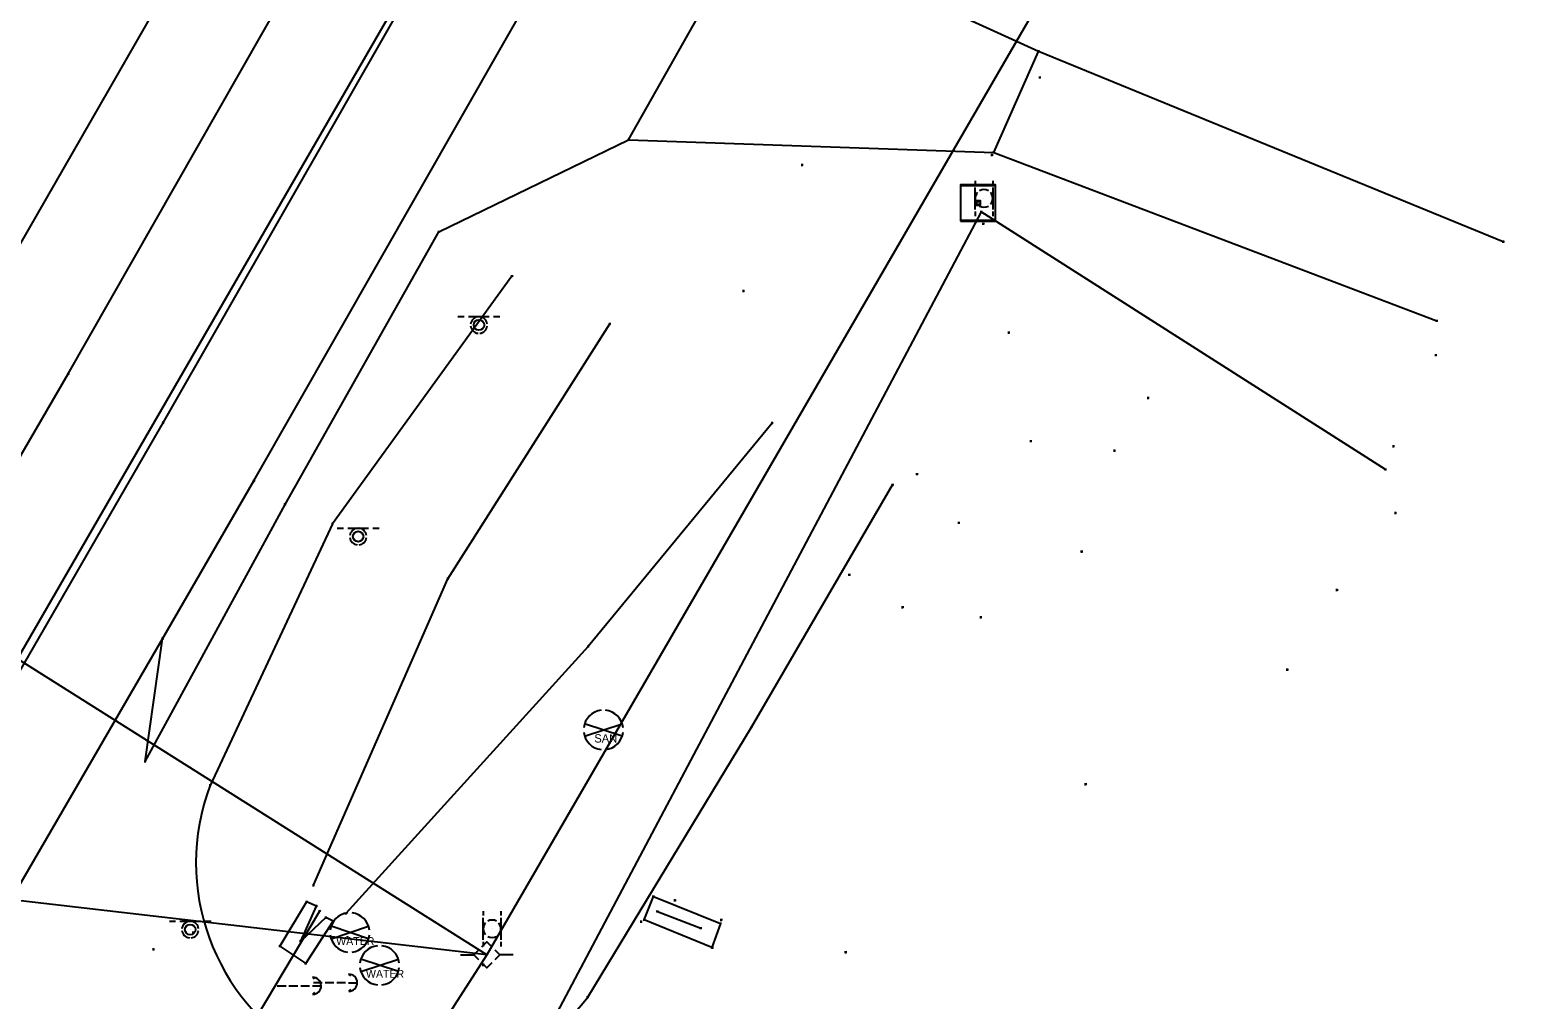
# Model space of a CAD drawing. Extents: x 1954856 to 2011933, y 399149 to 426294.
# Drawn here: x 2007162.2 to 2007333.7, y 403170.4 to 403280.8 of the extents above; entities that cross this region are included whole.
import ezdxf

# ---------------------------------------------------------------- set-up
doc = ezdxf.new("R2010")
doc.units = 0
for name, color, linetype in [('BankMent_ep', 7, 'Continuous'), ('BaselineSurvey', 7, 'Continuous'), ('ConcSlabs_ep', 7, 'Continuous'), ('DelineatorPost_ep', 7, 'Continuous'), ('Driveway_ep', 7, 'Continuous'), ('ElecAer_ep', 7, 'Continuous'), ('EndTreatMES_ep', 7, 'Continuous'), ('Fence_ep', 7, 'Continuous'), ('FlowLineInvert_ep', 7, 'Continuous'), ('GuyWireAnchor_ep', 7, 'Continuous'), ('MonumentCC_ep', 7, 'Continuous'), ('PavtAsphalt_ep', 7, 'Continuous'), ('PavtAsphaltCrown_ep', 7, 'Continuous'), ('PipeCulvert_ep', 7, 'Continuous'), ('PMRK_ep', 7, 'Continuous'), ('PointLocator_ep', 7, 'Continuous'), ('PoleElec_ep', 7, 'Continuous'), ('ShldrPaved_ep', 7, 'Continuous'), ('SignSingle_ep', 7, 'Continuous'), ('Trail_ep', 7, 'Continuous'), ('ValveCvrSewer_ep', 7, 'Continuous'), ('ValveCvrWater_ep', 7, 'Continuous'), ('WaterB_ep', 7, 'Continuous')]:
    doc.layers.add(name, color=color, linetype=linetype)

msp = doc.modelspace()

# ---------------------------------------------------------------- linework, layer by layer
at = {"layer": 'BankMent_ep'}
for p, q in [((2007216.98, 403252.81), (2007196.55, 403224.61)), ((2007244.24, 403201.46), (2007260.29, 403229.04)), ((2007196.55, 403224.61), (2007182.65, 403194.84)), ((2007225.6, 403170.73), (2007244.24, 403201.46))]:
    msp.add_line(p, q, dxfattribs=at)
for points in [[(2007194.39, 403183.47), (2007209.69, 403218.36), (2007228.12, 403247.37)], [(2007246.58, 403236.08), (2007225.66, 403210.64), (2007198.08, 403180.25)]]:
    msp.add_lwpolyline(points, dxfattribs=at)
msp.add_arc((2007205.94, 403186.01), 24.91, 159.2289, 322.1605, dxfattribs=at)
at = {"layer": 'BaselineSurvey'}
msp.add_lwpolyline([(2006095.1, 401364.22), (2006751.44, 402500.64), (2007687.69, 404121.69)], dxfattribs=at)
at = {"layer": 'ConcSlabs_ep'}
msp.add_lwpolyline([(2007240.7, 403179.12), (2007239.72, 403176.38), (2007232.04, 403179.54), (2007233.08, 403182.17)], close=True, dxfattribs=at)
at = {"layer": 'DelineatorPost_ep'}
for p, q in [((2007269.69, 403263.66), (2007269.69, 403263.16)), ((2007271.69, 403263.66), (2007271.69, 403263.16)), ((2007269.69, 403260.41), (2007269.69, 403262.91)), ((2007271.69, 403262.91), (2007271.69, 403260.41)), ((2007270.69, 403261.66), (2007270.69, 403261.66)), ((2007269.69, 403260.16), (2007269.69, 403259.66)), ((2007271.69, 403260.16), (2007271.69, 403259.66)), ((2007213.72, 403180.51), (2007213.72, 403180.01)), ((2007213.72, 403177.26), (2007213.72, 403179.76)), ((2007215.72, 403180.51), (2007215.72, 403180.01)), ((2007215.72, 403179.76), (2007215.72, 403177.26)), ((2007214.72, 403178.51), (2007214.72, 403178.51)), ((2007213.72, 403177.01), (2007213.72, 403176.51)), ((2007215.72, 403177.01), (2007215.72, 403176.51))]:
    msp.add_line(p, q, dxfattribs=at)
for centre, start, end in [((2007270.69, 403261.66), 138.5904, 221.4096), ((2007270.69, 403261.66), 60, 120), ((2007270.69, 403261.66), 318.5904, 41.4096), ((2007270.69, 403261.66), 240, 300), ((2007214.72, 403178.51), 138.5904, 221.4096), ((2007214.72, 403178.51), 60, 120), ((2007214.72, 403178.51), 318.5904, 41.4096), ((2007214.72, 403178.51), 240, 300)]:
    msp.add_arc(centre, 1, start, end, dxfattribs=at)
at = {"layer": 'Driveway_ep'}
msp.add_lwpolyline([(2007230.25, 403268.33), (2007271.8, 403266.88), (2007276.91, 403278.4), (2007244.3, 403293.28)], dxfattribs=at)
at = {"layer": 'ElecAer_ep'}
for points in [[(2007708.74, 404031.96), (2007465.98, 403610.27), (2007214.12, 403175.55), (2007112.5, 403239.66)], [(2007214.12, 403175.55), (2007004.92, 403199.79)], [(2007214.12, 403175.55), (2007202.74, 403157.81)]]:
    msp.add_lwpolyline(points, dxfattribs=at)
at = {"layer": 'EndTreatMES_ep'}
msp.add_lwpolyline([(2007193.61, 403181.59), (2007190.58, 403176.53), (2007193.51, 403174.56), (2007196.65, 403179.36), (2007195.79, 403179.78), (2007192.94, 403177.09), (2007194.74, 403181.1)], close=True, dxfattribs=at)
at = {"layer": 'Fence_ep'}
msp.add_lwpolyline([(2007316.39, 403230.79), (2007270.37, 403260.12), (2007212.64, 403151.1)], dxfattribs=at)
at = {"layer": 'FlowLineInvert_ep'}
for p, q in [((2007195.18, 403180.4), (2007195, 403180.58)), ((2007195.18, 403180.58), (2007195, 403180.4)), ((2007195.09, 403180.49), (2007195.09, 403180.49))]:
    msp.add_line(p, q, dxfattribs=at)
at = {"layer": 'GuyWireAnchor_ep'}
for p, q in [((2007194.3, 403172.99), (2007194.49, 403172.8)), ((2007198.4, 403173.34), (2007198.6, 403173.15)), ((2007190.27, 403172.03), (2007191.27, 403172.03)), ((2007191.6, 403172.03), (2007192.6, 403172.03)), ((2007192.94, 403172.03), (2007193.94, 403172.03)), ((2007194.27, 403172.02), (2007195.27, 403172.02)), ((2007194.31, 403171.05), (2007194.55, 403171.28)), ((2007194.38, 403172.38), (2007195.38, 403172.38)), ((2007195.27, 403172.02), (2007195.27, 403172.02)), ((2007195.71, 403172.38), (2007196.71, 403172.38)), ((2007197.04, 403172.38), (2007198.04, 403172.38)), ((2007198.38, 403172.37), (2007199.38, 403172.37)), ((2007198.42, 403171.4), (2007198.66, 403171.63)), ((2007199.38, 403172.37), (2007199.38, 403172.37))]:
    msp.add_line(p, q, dxfattribs=at)
for centre in [(2007194.3, 403172.02), (2007198.4, 403172.37)]:
    msp.add_arc(centre, 0.973, 271.14, 90.0059, dxfattribs=at)
at = {"layer": 'MonumentCC_ep'}
for p, q in [((2007270.01, 403261.2), (2007270.01, 403261.2)), ((2007270.02, 403261.09), (2007270.02, 403261.09))]:
    msp.add_line(p, q, dxfattribs=at)
for points in [[(2007268.01, 403259.2), (2007272.01, 403259.2), (2007272.01, 403263.2), (2007268.01, 403263.2), (2007268.01, 403259.2)], [(2007268.02, 403259.09), (2007272.02, 403259.09), (2007272.02, 403263.1), (2007268.02, 403263.1), (2007268.02, 403259.09)]]:
    msp.add_lwpolyline(points, dxfattribs=at)
for points in [[(2007269.77, 403260.97), (2007269.77, 403261.44), (2007270.24, 403261.44), (2007270.24, 403260.97)], [(2007269.78, 403260.86), (2007269.78, 403261.33), (2007270.26, 403261.33), (2007270.26, 403260.86)]]:
    msp.add_lwpolyline(points, close=True, dxfattribs=at)
at = {"layer": 'PavtAsphalt_ep'}
msp.add_line((2007175.25, 403197.55), (2007177.23, 403211.53), dxfattribs=at)
for points in [[(2007177.23, 403211.53), (2007187.62, 403229.5), (2007234.7, 403312.11), (2007271.67, 403375.49), (2007306.65, 403435.49), (2007349.66, 403509.58), (2007385.36, 403571.59), (2007428.89, 403647.4), (2007469.25, 403717.9)], [(2006897.05, 402800.14), (2006944.17, 402881.58), (2006996.71, 402973.18), (2007032.59, 403035.44), (2007081.34, 403118.81), (2007155.79, 403247.38), (2007202.92, 403329.48)]]:
    msp.add_lwpolyline(points, dxfattribs=at)
at = {"layer": 'PavtAsphaltCrown_ep'}
msp.add_lwpolyline([(2006917.74, 402787.19), (2006964.28, 402867.82), (2007017.94, 402960.42), (2007054.7, 403023.68), (2007102.51, 403106.5), (2007177.29, 403236.13), (2007223.74, 403317.44)], dxfattribs=at)
at = {"layer": 'PipeCulvert_ep'}
msp.add_lwpolyline([(2007154.82, 403112.92), (2007195.09, 403180.49)], dxfattribs=at)
at = {"layer": 'PMRK_ep'}
for points in [[(2006907.45, 402793.37), (2006954.17, 402875.59), (2007007.43, 402967.36), (2007044.03, 403029.48), (2007091.72, 403112.9), (2007166.49, 403241.69), (2007213.16, 403323.66)], [(2006926.96, 402780.55), (2006975.08, 402862.21), (2007028.52, 402954.63), (2007065.46, 403018.91), (2007177.23, 403211.53)]]:
    msp.add_lwpolyline(points, dxfattribs=at)
at = {"layer": 'PointLocator_ep'}
for p, q in [((2007277.04, 403278.4), (2007276.79, 403278.4)), ((2007276.91, 403278.28), (2007276.91, 403278.53)), ((2007276.91, 403278.4), (2007276.91, 403278.4)), ((2007277.17, 403275.43), (2007276.92, 403275.43)), ((2007277.05, 403275.3), (2007277.05, 403275.55)), ((2007277.05, 403275.43), (2007277.05, 403275.43)), ((2007230.38, 403268.33), (2007230.13, 403268.33)), ((2007230.25, 403268.21), (2007230.25, 403268.46)), ((2007230.25, 403268.33), (2007230.25, 403268.33)), ((2007250.13, 403265.47), (2007249.88, 403265.47)), ((2007250, 403265.34), (2007250, 403265.59)), ((2007250, 403265.47), (2007250, 403265.47)), ((2007271.72, 403266.6), (2007271.47, 403266.6)), ((2007271.59, 403266.48), (2007271.59, 403266.73)), ((2007271.59, 403266.6), (2007271.59, 403266.6)), ((2007271.93, 403266.88), (2007271.68, 403266.88)), ((2007271.8, 403266.76), (2007271.8, 403267.01)), ((2007271.8, 403266.88), (2007271.8, 403266.88)), ((2007270.37, 403260), (2007270.37, 403260.25)), ((2007270.49, 403260.12), (2007270.24, 403260.12)), ((2007270.37, 403260.12), (2007270.37, 403260.12)), ((2007270.74, 403258.77), (2007270.49, 403258.77)), ((2007270.61, 403258.65), (2007270.61, 403258.9)), ((2007270.61, 403258.77), (2007270.61, 403258.77)), ((2007208.8, 403257.87), (2007208.55, 403257.87)), ((2007208.67, 403257.74), (2007208.67, 403257.99)), ((2007208.67, 403257.87), (2007208.67, 403257.87)), ((2007329.79, 403256.61), (2007329.79, 403256.86)), ((2007329.92, 403256.73), (2007329.67, 403256.73)), ((2007329.79, 403256.73), (2007329.79, 403256.73)), ((2007217.11, 403252.81), (2007216.86, 403252.81)), ((2007216.98, 403252.69), (2007216.98, 403252.94)), ((2007216.98, 403252.81), (2007216.98, 403252.81)), ((2007243.45, 403251.12), (2007243.2, 403251.12)), ((2007243.32, 403250.99), (2007243.32, 403251.24)), ((2007243.32, 403251.12), (2007243.32, 403251.12)), ((2007228.24, 403247.37), (2007227.99, 403247.37)), ((2007228.12, 403247.25), (2007228.12, 403247.5)), ((2007228.12, 403247.37), (2007228.12, 403247.37)), ((2007273.53, 403246.25), (2007273.53, 403246.5)), ((2007322.35, 403247.72), (2007322.1, 403247.72)), ((2007322.23, 403247.6), (2007322.23, 403247.85)), ((2007322.23, 403247.72), (2007322.23, 403247.72)), ((2007273.65, 403246.38), (2007273.4, 403246.38)), ((2007273.53, 403246.38), (2007273.53, 403246.38)), ((2007322.24, 403243.81), (2007321.99, 403243.81)), ((2007322.11, 403243.69), (2007322.11, 403243.94)), ((2007322.11, 403243.81), (2007322.11, 403243.81)), ((2007166.62, 403241.69), (2007166.37, 403241.69)), ((2007166.49, 403241.56), (2007166.49, 403241.81)), ((2007166.49, 403241.69), (2007166.49, 403241.69)), ((2007289.5, 403238.95), (2007289.25, 403238.95)), ((2007289.37, 403238.82), (2007289.37, 403239.07)), ((2007289.37, 403238.95), (2007289.37, 403238.95)), ((2007177.29, 403236.01), (2007177.29, 403236.26)), ((2007246.58, 403235.96), (2007246.58, 403236.21)), ((2007177.42, 403236.13), (2007177.17, 403236.13)), ((2007177.29, 403236.13), (2007177.29, 403236.13)), ((2007246.71, 403236.08), (2007246.46, 403236.08)), ((2007246.58, 403236.08), (2007246.58, 403236.08)), ((2007276.15, 403234.03), (2007275.9, 403234.03)), ((2007276.02, 403233.9), (2007276.02, 403234.15)), ((2007276.02, 403234.03), (2007276.02, 403234.03)), ((2007285.67, 403232.94), (2007285.42, 403232.94)), ((2007285.54, 403232.81), (2007285.54, 403233.06)), ((2007285.54, 403232.94), (2007285.54, 403232.94)), ((2007317.41, 403233.44), (2007317.16, 403233.44)), ((2007317.29, 403233.32), (2007317.29, 403233.57)), ((2007317.29, 403233.44), (2007317.29, 403233.44)), ((2007187.75, 403229.5), (2007187.5, 403229.5)), ((2007187.62, 403229.37), (2007187.62, 403229.62)), ((2007187.62, 403229.5), (2007187.62, 403229.5)), ((2007263.2, 403230.28), (2007262.95, 403230.28)), ((2007263.08, 403230.15), (2007263.08, 403230.4)), ((2007263.08, 403230.28), (2007263.08, 403230.28)), ((2007316.51, 403230.79), (2007316.26, 403230.79)), ((2007316.39, 403230.67), (2007316.39, 403230.92)), ((2007316.39, 403230.79), (2007316.39, 403230.79)), ((2007260.42, 403229.04), (2007260.17, 403229.04)), ((2007260.29, 403228.92), (2007260.29, 403229.17)), ((2007260.29, 403229.04), (2007260.29, 403229.04)), ((2007191.29, 403226.83), (2007191.04, 403226.83)), ((2007191.17, 403226.71), (2007191.17, 403226.96)), ((2007191.17, 403226.83), (2007191.17, 403226.83)), ((2007317.52, 403225.72), (2007317.52, 403225.97)), ((2007196.68, 403224.61), (2007196.43, 403224.61)), ((2007196.55, 403224.49), (2007196.55, 403224.74)), ((2007196.55, 403224.61), (2007196.55, 403224.61)), ((2007267.96, 403224.73), (2007267.71, 403224.73)), ((2007267.84, 403224.61), (2007267.84, 403224.86)), ((2007267.84, 403224.73), (2007267.84, 403224.73)), ((2007317.64, 403225.84), (2007317.39, 403225.84)), ((2007317.52, 403225.84), (2007317.52, 403225.84)), ((2007281.93, 403221.45), (2007281.68, 403221.45)), ((2007281.81, 403221.33), (2007281.81, 403221.58)), ((2007281.81, 403221.45), (2007281.81, 403221.45)), ((2007209.81, 403218.36), (2007209.56, 403218.36)), ((2007209.69, 403218.24), (2007209.69, 403218.49)), ((2007209.69, 403218.36), (2007209.69, 403218.36)), ((2007255.5, 403218.81), (2007255.25, 403218.81)), ((2007255.38, 403218.68), (2007255.38, 403218.93)), ((2007255.38, 403218.81), (2007255.38, 403218.81)), ((2007310.98, 403217.08), (2007310.73, 403217.08)), ((2007310.85, 403216.96), (2007310.85, 403217.21)), ((2007310.85, 403217.08), (2007310.85, 403217.08)), ((2007261.56, 403215.11), (2007261.31, 403215.11)), ((2007261.44, 403214.99), (2007261.44, 403215.24)), ((2007261.44, 403215.11), (2007261.44, 403215.11)), ((2007270.46, 403213.97), (2007270.21, 403213.97)), ((2007270.34, 403213.85), (2007270.34, 403214.1)), ((2007270.34, 403213.97), (2007270.34, 403213.97)), ((2007177.35, 403211.53), (2007177.1, 403211.53)), ((2007177.23, 403211.41), (2007177.23, 403211.66)), ((2007177.23, 403211.53), (2007177.23, 403211.53)), ((2007225.78, 403210.64), (2007225.53, 403210.64)), ((2007225.66, 403210.52), (2007225.66, 403210.77)), ((2007225.66, 403210.64), (2007225.66, 403210.64)), ((2007305.33, 403208.01), (2007305.08, 403208.01)), ((2007305.21, 403207.88), (2007305.21, 403208.13)), ((2007305.21, 403208.01), (2007305.21, 403208.01)), ((2007244.36, 403201.46), (2007244.11, 403201.46)), ((2007244.24, 403201.34), (2007244.24, 403201.59)), ((2007244.24, 403201.46), (2007244.24, 403201.46)), ((2007175.37, 403197.55), (2007175.12, 403197.55)), ((2007175.25, 403197.43), (2007175.25, 403197.68)), ((2007175.25, 403197.55), (2007175.25, 403197.55)), ((2007282.26, 403194.84), (2007282.26, 403195.09)), ((2007182.77, 403194.84), (2007182.52, 403194.84)), ((2007182.65, 403194.72), (2007182.65, 403194.97)), ((2007182.65, 403194.84), (2007182.65, 403194.84)), ((2007282.38, 403194.96), (2007282.13, 403194.96)), ((2007282.26, 403194.96), (2007282.26, 403194.96)), ((2007194.52, 403183.47), (2007194.27, 403183.47)), ((2007194.39, 403183.34), (2007194.39, 403183.59)), ((2007194.39, 403183.47), (2007194.39, 403183.47)), ((2007193.74, 403181.59), (2007193.49, 403181.59)), ((2007193.61, 403181.46), (2007193.61, 403181.71)), ((2007193.61, 403181.59), (2007193.61, 403181.59)), ((2007233.2, 403182.17), (2007232.95, 403182.17)), ((2007233.08, 403182.05), (2007233.08, 403182.3)), ((2007233.08, 403182.17), (2007233.08, 403182.17)), ((2007235.66, 403181.74), (2007235.41, 403181.74)), ((2007235.53, 403181.62), (2007235.53, 403181.87)), ((2007235.53, 403181.74), (2007235.53, 403181.74)), ((2007194.87, 403181.1), (2007194.62, 403181.1)), ((2007194.74, 403180.98), (2007194.74, 403181.23)), ((2007194.74, 403181.1), (2007194.74, 403181.1)), ((2007195.92, 403179.78), (2007195.67, 403179.78)), ((2007195.79, 403179.66), (2007195.79, 403179.91)), ((2007195.79, 403179.78), (2007195.79, 403179.78)), ((2007198.21, 403180.25), (2007197.96, 403180.25)), ((2007198.08, 403180.12), (2007198.08, 403180.37)), ((2007198.08, 403180.25), (2007198.08, 403180.25)), ((2007232.04, 403179.41), (2007232.04, 403179.66)), ((2007233.65, 403180.48), (2007233.4, 403180.48)), ((2007233.53, 403180.36), (2007233.53, 403180.61)), ((2007233.53, 403180.48), (2007233.53, 403180.48)), ((2007240.8, 403179.39), (2007240.8, 403179.64)), ((2007180.85, 403178.07), (2007180.6, 403178.07)), ((2007180.72, 403177.94), (2007180.72, 403178.19)), ((2007180.72, 403178.07), (2007180.72, 403178.07)), ((2007196.77, 403179.36), (2007196.52, 403179.36)), ((2007196.65, 403179.23), (2007196.65, 403179.48)), ((2007196.65, 403179.36), (2007196.65, 403179.36)), ((2007231.81, 403179.32), (2007231.56, 403179.32)), ((2007231.69, 403179.2), (2007231.69, 403179.45)), ((2007231.69, 403179.32), (2007231.69, 403179.32)), ((2007232.16, 403179.54), (2007231.91, 403179.54)), ((2007232.04, 403179.54), (2007232.04, 403179.54)), ((2007238.6, 403178.58), (2007238.35, 403178.58)), ((2007238.47, 403178.45), (2007238.47, 403178.7)), ((2007238.47, 403178.58), (2007238.47, 403178.58)), ((2007240.83, 403179.12), (2007240.58, 403179.12)), ((2007240.93, 403179.52), (2007240.68, 403179.52)), ((2007240.7, 403178.99), (2007240.7, 403179.24)), ((2007240.7, 403179.12), (2007240.7, 403179.12)), ((2007240.8, 403179.52), (2007240.8, 403179.52)), ((2007176.31, 403176.17), (2007176.06, 403176.17)), ((2007176.19, 403176.04), (2007176.19, 403176.29)), ((2007176.19, 403176.17), (2007176.19, 403176.17)), ((2007190.7, 403176.53), (2007190.45, 403176.53)), ((2007190.58, 403176.4), (2007190.58, 403176.65)), ((2007190.58, 403176.53), (2007190.58, 403176.53)), ((2007193.07, 403177.09), (2007192.82, 403177.09)), ((2007192.94, 403176.97), (2007192.94, 403177.22)), ((2007192.94, 403177.09), (2007192.94, 403177.09)), ((2007198.39, 403177.53), (2007198.14, 403177.53)), ((2007198.27, 403177.41), (2007198.27, 403177.66)), ((2007198.27, 403177.53), (2007198.27, 403177.53)), ((2007239.85, 403176.38), (2007239.6, 403176.38)), ((2007239.92, 403176.36), (2007239.67, 403176.36)), ((2007239.72, 403176.25), (2007239.72, 403176.5)), ((2007239.72, 403176.38), (2007239.72, 403176.38)), ((2007239.79, 403176.23), (2007239.79, 403176.48)), ((2007239.79, 403176.36), (2007239.79, 403176.36)), ((2007193.63, 403174.56), (2007193.38, 403174.56)), ((2007193.51, 403174.44), (2007193.51, 403174.69)), ((2007193.51, 403174.56), (2007193.51, 403174.56)), ((2007213.72, 403174.27), (2007213.72, 403174.52)), ((2007255.08, 403175.84), (2007254.83, 403175.84)), ((2007254.96, 403175.71), (2007254.96, 403175.96)), ((2007254.96, 403175.84), (2007254.96, 403175.84)), ((2007213.84, 403174.39), (2007213.59, 403174.39)), ((2007213.72, 403174.39), (2007213.72, 403174.39)), ((2007225.73, 403170.73), (2007225.48, 403170.73)), ((2007225.6, 403170.6), (2007225.6, 403170.85)), ((2007225.6, 403170.73), (2007225.6, 403170.73))]:
    msp.add_line(p, q, dxfattribs=at)
at = {"layer": 'PoleElec_ep'}
for p, q in [((2007211.13, 403175.55), (2007212.63, 403175.55)), ((2007212.63, 403175.55), (2007213.2, 403176.12)), ((2007213.2, 403174.99), (2007212.63, 403175.55)), ((2007214.12, 403175.55), (2007214.12, 403175.55)), ((2007217.11, 403175.55), (2007215.61, 403175.55))]:
    msp.add_line(p, q, dxfattribs=at)
for points in [[(2007213.55, 403176.47), (2007214.12, 403177.04), (2007214.69, 403176.47)], [(2007214.69, 403174.63), (2007214.12, 403174.07), (2007213.55, 403174.63)], [(2007215.04, 403176.12), (2007215.61, 403175.55), (2007215.04, 403174.99)]]:
    msp.add_lwpolyline(points, dxfattribs=at)
at = {"layer": 'ShldrPaved_ep'}
msp.add_lwpolyline([(2007175.25, 403197.55), (2007191.17, 403226.83), (2007208.67, 403257.87), (2007230.25, 403268.33), (2007244.3, 403293.28), (2007238.53, 403309.66), (2007275.3, 403373.39), (2007310.01, 403433.33), (2007352.71, 403507.64), (2007388.49, 403569.73), (2007431.91, 403645.32), (2007472.11, 403716.08)], dxfattribs=at)
at = {"layer": 'SignSingle_ep'}
for p, q in [((2007210.84, 403248.2), (2007211.54, 403248.2)), ((2007212.04, 403248.2), (2007214.39, 403248.2)), ((2007213.22, 403247.25), (2007213.22, 403247.25)), ((2007214.89, 403248.2), (2007215.59, 403248.2)), ((2007197.11, 403224.12), (2007197.81, 403224.12)), ((2007198.31, 403224.12), (2007200.66, 403224.12)), ((2007199.48, 403223.17), (2007199.48, 403223.17)), ((2007201.16, 403224.12), (2007201.86, 403224.12)), ((2007178, 403179.37), (2007178.7, 403179.37)), ((2007179.2, 403179.37), (2007181.55, 403179.37)), ((2007180.37, 403178.42), (2007180.37, 403178.42)), ((2007182.05, 403179.37), (2007182.75, 403179.37))]:
    msp.add_line(p, q, dxfattribs=at)
for centre in [(2007213.22, 403247.25), (2007199.48, 403223.17), (2007180.37, 403178.42)]:
    msp.add_circle(centre, 0.594, dxfattribs=at)
for centre, start, end in [((2007213.22, 403247.25), 96.0423, 173.9577), ((2007213.22, 403247.25), 186.0423, 263.9577), ((2007213.22, 403247.25), 6.0423, 83.9577), ((2007213.22, 403247.25), 276.0423, 353.9577), ((2007199.48, 403223.17), 96.0423, 173.9577), ((2007199.48, 403223.17), 186.0423, 263.9577), ((2007199.48, 403223.17), 6.0423, 83.9577), ((2007199.48, 403223.17), 276.0423, 353.9577), ((2007180.37, 403178.42), 96.0423, 173.9577), ((2007180.37, 403178.42), 186.0423, 263.9577), ((2007180.37, 403178.42), 6.0423, 83.9577), ((2007180.37, 403178.42), 276.0423, 353.9577)]:
    msp.add_arc(centre, 0.95, start, end, dxfattribs=at)
at = {"layer": 'Trail_ep'}
for points in [[(2007329.79, 403256.73), (2007276.91, 403278.4)], [(2007271.8, 403266.88), (2007322.23, 403247.72)]]:
    msp.add_lwpolyline(points, dxfattribs=at)
at = {"layer": 'ValveCvrSewer_ep'}
for p, q in [((2007225.25, 403200.44), (2007229.52, 403201.86)), ((2007229.52, 403200.44), (2007225.25, 403201.86)), ((2007227.39, 403201.15), (2007227.39, 403201.15))]:
    msp.add_line(p, q, dxfattribs=at)
for start, end in [(96.3794, 173.6206), (6.3794, 83.6206), (186.3794, 263.6206), (276.3794, 353.6206)]:
    msp.add_arc((2007227.39, 403201.15), 2.25, start, end, dxfattribs=at)
at = {"layer": 'ValveCvrWater_ep'}
for p, q in [((2007196.39, 403177.37), (2007200.66, 403178.8)), ((2007200.66, 403177.37), (2007196.39, 403178.8)), ((2007198.53, 403178.09), (2007198.53, 403178.09)), ((2007199.79, 403173.64), (2007204.06, 403175.06)), ((2007204.06, 403173.64), (2007199.79, 403175.06)), ((2007201.92, 403174.35), (2007201.92, 403174.35))]:
    msp.add_line(p, q, dxfattribs=at)
for centre, start, end in [((2007198.53, 403178.09), 96.3794, 173.6206), ((2007198.53, 403178.09), 6.3794, 83.6206), ((2007198.53, 403178.09), 186.3794, 263.6206), ((2007198.53, 403178.09), 276.3794, 353.6206), ((2007201.92, 403174.35), 96.3794, 173.6206), ((2007201.92, 403174.35), 6.3794, 83.6206), ((2007201.92, 403174.35), 186.3794, 263.6206), ((2007201.92, 403174.35), 276.3794, 353.6206)]:
    msp.add_arc(centre, 2.25, start, end, dxfattribs=at)
at = {"layer": 'WaterB_ep'}
msp.add_lwpolyline([(2007233.53, 403180.48), (2007238.47, 403178.58)], dxfattribs=at)

# ---------------------------------------------------------------- texts
at = {"layer": 'ValveCvrSewer_ep'}
msp.add_text('SAN', height=0.95, dxfattribs=at).set_placement((2007226.35, 403199.71))
at = {"layer": 'ValveCvrWater_ep'}
for p in [(2007196.98, 403176.66), (2007200.37, 403172.93)]:
    msp.add_text('WATER', height=0.9, dxfattribs=at).set_placement(p)

doc.saveas('drawing.dxf')
